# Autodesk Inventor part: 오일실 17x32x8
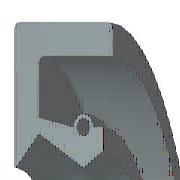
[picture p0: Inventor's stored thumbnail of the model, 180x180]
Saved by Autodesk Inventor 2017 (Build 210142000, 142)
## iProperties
IsCustomPart: 1
Created: 2012-02
Part Number: 오일실 17x32x8
Material: 고무
Description: 오일-실
Document SubType Name: Modeling
Standard: KS B 2804
Designer: mduedu
Standards Organization: KS
Language: ko-KR
Size Designation: D - 17 32 8
Categories: <MemberInstance><Categories><Category DisplayName="샤프트 부품" InternalName="7f7aeb1f-a693-4053-b835-cee3144e0d98" Mnemonic="SHFT"><Category DisplayName="실링" Intern
Density: 0.93 g/cm^3
Appearance: 고무 - 검은색 - 버전 1.1
Mass: 2.28027 g
Surface Area: 32.1224 cm^2
Volume: 2.45191 cm^3
Author: mduedu
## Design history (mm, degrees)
revolve "본체" stored, may be unused: angle "d17" = 90 deg
revolve "스프링1" stored, may be unused: angle "d18" = 90 deg
body "Solid1"
sketch "스케치1"
  geometry: L1 (0, 16)-(8, 16); L2 (8, 14.25)-(1.75, 14.25); L3 (1.75, 10.25)-(4.9, 8.5); L4 (4.9, 8.5)-(0, 8.5); L5 (0, 0)-(9.586, 0) reference; L6 (4.9, 8.5)-(6.3, 9.375); L7 (0, 18)-(0, -3) reference; L8 (-1.941, 0)-(11.507, 0) reference; L9 (4.2, 10.6)-(1.75, 11.21); L10 (1.75, 11.21)-(1.75, 14.25); L11 (0, 16)-(0, 8.588); L12 (4.9, 8.5)-(0, 8.5); L13 (1.75, 10.25)-(0.152, 8.528); L14 (8, 16)-(8, 14.25); L15 (5.6, 10.6)-(6.3, 10.6); L16 (6.3, 10.6)-(6.3, 9.375); C1 r 0.455 at (4.9, 10.6); A1 r 0.7 centre (4.9, 10.6) between (5.6, 10.6) and (4.2, 10.6); A2 r 0.088 centre (0.088, 8.588) between (0, 8.588) and (0.152, 8.528); 1 further point
  constraints: 28 end point, 5 horizontal alignment, 5 point on line, 4 point on circle, 4 vertical alignment, 3 centre point, 3 tangent, 2 collinear, 2 horizontal, 2 perpendicular, 1 coincident, 1 parallel
  dimensions: "d0" = 32 diameter of L1 L5 (= SD2); "d1" = 1.75 distance of L1.end L2.start (= SD); "d2" = 0.91 diameter of C1 (= SPDI); "d3" = 1.4 diameter of A1 (= SPDA); "d4" = 17 diameter of L3.end L5 (= NND); "d5" = 20.5 diameter of L3.start L5 (= TKDM); "d7" = 22.42 diameter of L9.end L5 (= TKDM + 0.24 x SWDT); "d8" = 1.75 distance between parallel lines of L11 L10 (= SD); "d9" = 4.9 distance from line of L11 C1.centre (= SPDST); "d10" = 21.2 diameter of C1.centre L5 (= HLDM); "d11" = 0.0875 radius of A2 (= 0.25 x LAB); "d12" = 6.3 distance between parallel lines of L11 L16 (= SDI); "d13" = 18.75 diameter of L6.end L5 (= ABDM); "d14" = 8 distance from line of L11 L1.end (= SWDT)
fillet "모깎기1" dims "d6" = 0.3 (= RR)
other parameters: "SD2" = 32 [user parameter; used in 1 equation term], "SWDT" = 8 [user parameter; used in 2 equation terms], "RR" = 0.3 [user parameter; used in 1 equation term], "SD" = 1.75 [user parameter; used in 2 equation terms], "NND" = 17 [user parameter; used in 1 equation term], "SPDA" = 1.4 [user parameter; used in 1 equation term], "SPDI" = 0.91 [user parameter; used in 1 equation term], "TKDM" = 20.5 [user parameter; used in 2 equation terms], "HLDM" = 21.2 [user parameter; used in 1 equation term], "ABDM" = 18.75 [user parameter; used in 1 equation term], "SDI" = 6.3 [user parameter; used in 1 equation term], "SPDST" = 4.9 [user parameter; used in 1 equation term], "LAB" = 0.35 [user parameter; used in 1 equation term], "d15" = 0, "d16" = 0, "d19" = 0
